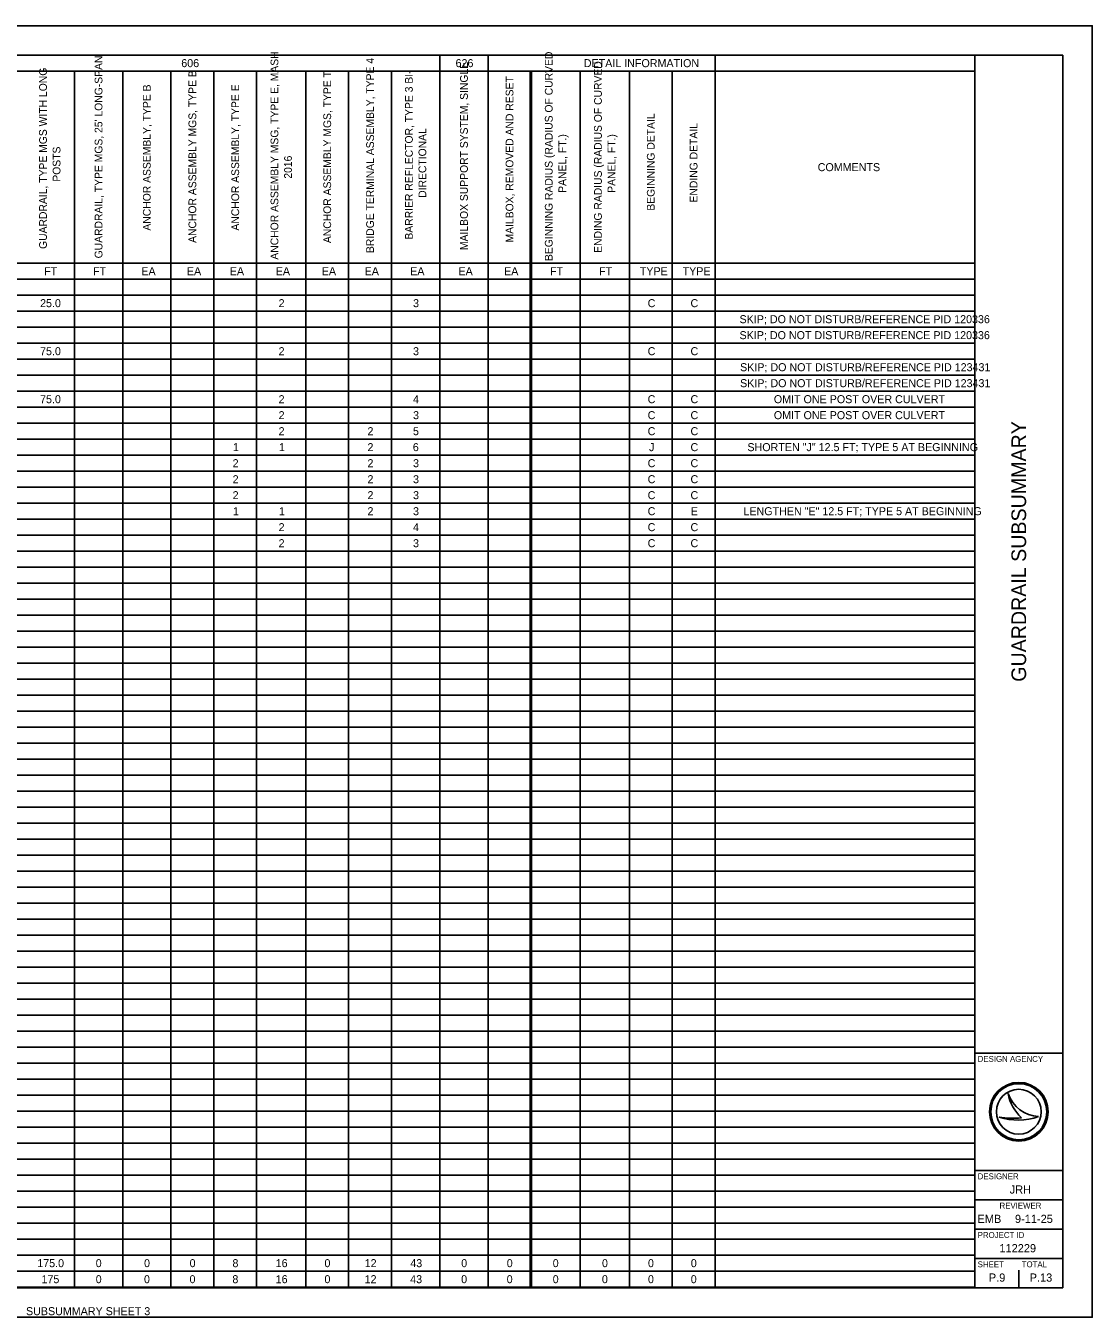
# Model space of a CAD drawing. Extents: x 0 to 34, y -0.3 to 22.
# Drawn here: x 15.84 to 34, y 0 to 22 of the extents above; entities that cross this region are included whole.
import ezdxf

# ---------------------------------------------------------------- set-up
doc = ezdxf.new("R2010")
doc.units = 0
for name, color, linetype in [('Default', 7, 'Continuous'), ('SH_Border', 7, 'Continuous'), ('SH_Cut_Line', 7, 'Continuous'), ('SH_Data', 7, 'Continuous')]:
    doc.layers.add(name, color=color, linetype=linetype)

msp = doc.modelspace()

# ---------------------------------------------------------------- linework, layer by layer
at = {"layer": 'Default'}
for p, q in [((1.5, 21.5), (31.999, 21.5)), ((22.888, 21.5), (22.888, 0.511)), ((23.711, 21.5), (23.711, 0.511)), ((27.576, 21.5), (27.576, 0.511)), ((31.999, 21.5), (31.999, 0.511)), ((5.582, 21.227), (24.451, 21.227)), ((16.664, 21.227), (16.664, 0.511)), ((17.487, 21.227), (17.487, 0.511)), ((18.31, 21.227), (18.31, 0.511)), ((19.039, 21.227), (19.039, 0.511)), ((19.769, 21.227), (19.769, 0.511)), ((20.607, 21.227), (20.607, 0.511)), ((21.336, 21.227), (21.336, 0.511)), ((22.066, 21.227), (22.066, 0.511)), ((24.43, 21.227), (31.999, 21.227)), ((24.43, 21.227), (24.43, 0.511)), ((24.451, 21.227), (24.451, 0.511)), ((25.279, 21.227), (25.279, 0.511)), ((26.117, 21.227), (26.117, 0.511)), ((26.846, 21.227), (26.846, 0.511)), ((5.582, 17.956), (24.43, 17.956)), ((24.451, 17.956), (31.999, 17.956)), ((1.5, 17.684), (24.43, 17.684)), ((24.451, 17.684), (31.999, 17.684)), ((1.5, 17.411), (24.43, 17.411)), ((24.451, 17.411), (31.999, 17.411)), ((1.5, 17.139), (24.43, 17.139)), ((24.451, 17.139), (31.999, 17.139)), ((1.5, 16.866), (24.43, 16.866)), ((24.451, 16.866), (31.999, 16.866)), ((1.5, 16.593), (24.43, 16.593)), ((24.451, 16.593), (31.999, 16.593)), ((1.5, 16.321), (24.43, 16.321)), ((24.451, 16.321), (31.999, 16.321)), ((1.5, 16.048), (24.43, 16.048)), ((24.451, 16.048), (31.999, 16.048)), ((1.5, 15.776), (24.43, 15.776)), ((24.451, 15.776), (31.999, 15.776)), ((1.5, 15.503), (24.43, 15.503)), ((24.451, 15.503), (31.999, 15.503)), ((1.5, 15.231), (24.43, 15.231)), ((24.451, 15.231), (31.999, 15.231)), ((1.5, 14.958), (24.43, 14.958)), ((24.451, 14.958), (31.999, 14.958)), ((1.5, 14.685), (24.43, 14.685)), ((24.451, 14.685), (31.999, 14.685)), ((1.5, 14.413), (24.43, 14.413)), ((24.451, 14.413), (31.999, 14.413)), ((1.5, 14.14), (24.43, 14.14)), ((24.451, 14.14), (31.999, 14.14)), ((1.5, 13.868), (24.43, 13.868)), ((24.451, 13.868), (31.999, 13.868)), ((1.5, 13.595), (24.43, 13.595)), ((24.451, 13.595), (31.999, 13.595)), ((1.5, 13.322), (24.43, 13.322)), ((24.451, 13.322), (31.999, 13.322)), ((1.5, 13.05), (24.43, 13.05)), ((24.451, 13.05), (31.999, 13.05)), ((1.5, 12.777), (24.43, 12.777)), ((24.451, 12.777), (31.999, 12.777)), ((1.5, 12.505), (24.43, 12.505)), ((24.451, 12.505), (31.999, 12.505)), ((1.5, 12.232), (24.43, 12.232)), ((24.451, 12.232), (31.999, 12.232)), ((1.5, 11.96), (24.43, 11.96)), ((24.451, 11.96), (31.999, 11.96)), ((1.5, 11.687), (24.43, 11.687)), ((24.451, 11.687), (31.999, 11.687)), ((1.5, 11.414), (24.43, 11.414)), ((24.451, 11.414), (31.999, 11.414)), ((1.5, 11.142), (24.43, 11.142)), ((24.451, 11.142), (31.999, 11.142)), ((1.5, 10.869), (24.43, 10.869)), ((24.451, 10.869), (31.999, 10.869)), ((1.5, 10.597), (24.43, 10.597)), ((24.451, 10.597), (31.999, 10.597)), ((1.5, 10.324), (24.43, 10.324)), ((24.451, 10.324), (31.999, 10.324)), ((1.5, 10.051), (24.43, 10.051)), ((24.451, 10.051), (31.999, 10.051)), ((1.5, 9.779), (24.43, 9.779)), ((24.451, 9.779), (31.999, 9.779)), ((1.5, 9.506), (24.43, 9.506)), ((24.451, 9.506), (31.999, 9.506)), ((1.5, 9.234), (24.43, 9.234)), ((24.451, 9.234), (31.999, 9.234)), ((1.5, 8.961), (24.43, 8.961)), ((24.451, 8.961), (31.999, 8.961)), ((1.5, 8.689), (24.43, 8.689)), ((24.451, 8.689), (31.999, 8.689)), ((1.5, 8.416), (24.43, 8.416)), ((24.451, 8.416), (31.999, 8.416)), ((1.5, 8.143), (24.43, 8.143)), ((24.451, 8.143), (31.999, 8.143)), ((1.5, 7.871), (24.43, 7.871)), ((24.451, 7.871), (31.999, 7.871)), ((1.5, 7.598), (24.43, 7.598)), ((24.451, 7.598), (31.999, 7.598)), ((1.5, 7.326), (24.43, 7.326)), ((24.451, 7.326), (31.999, 7.326)), ((1.5, 7.053), (24.43, 7.053)), ((24.451, 7.053), (31.999, 7.053)), ((1.5, 6.78), (24.43, 6.78)), ((24.451, 6.78), (31.999, 6.78)), ((1.5, 6.508), (24.43, 6.508)), ((24.451, 6.508), (31.999, 6.508)), ((1.5, 6.235), (24.43, 6.235)), ((24.451, 6.235), (31.999, 6.235)), ((1.5, 5.963), (24.43, 5.963)), ((24.451, 5.963), (31.999, 5.963)), ((1.5, 5.69), (24.43, 5.69)), ((24.451, 5.69), (31.999, 5.69)), ((1.5, 5.418), (24.43, 5.418)), ((24.451, 5.418), (31.999, 5.418)), ((1.5, 5.145), (24.43, 5.145)), ((24.451, 5.145), (31.999, 5.145)), ((1.5, 4.872), (24.43, 4.872)), ((24.451, 4.872), (31.999, 4.872)), ((1.5, 4.6), (24.43, 4.6)), ((24.451, 4.6), (31.999, 4.6)), ((1.5, 4.327), (24.43, 4.327)), ((24.451, 4.327), (31.999, 4.327)), ((1.5, 4.055), (24.43, 4.055)), ((24.451, 4.055), (31.999, 4.055)), ((1.5, 3.782), (24.43, 3.782)), ((24.451, 3.782), (31.999, 3.782)), ((1.5, 3.509), (24.43, 3.509)), ((24.451, 3.509), (31.999, 3.509)), ((1.5, 3.237), (24.43, 3.237)), ((24.451, 3.237), (31.999, 3.237)), ((1.5, 2.964), (24.43, 2.964)), ((24.451, 2.964), (31.999, 2.964)), ((1.5, 2.692), (24.43, 2.692)), ((24.451, 2.692), (31.999, 2.692)), ((1.5, 2.419), (24.43, 2.419)), ((24.451, 2.419), (31.999, 2.419)), ((1.5, 2.147), (24.43, 2.147)), ((24.451, 2.147), (31.999, 2.147)), ((1.5, 1.874), (24.43, 1.874)), ((24.451, 1.874), (31.999, 1.874)), ((1.5, 1.601), (24.43, 1.601)), ((24.451, 1.601), (31.999, 1.601)), ((1.5, 1.329), (24.43, 1.329)), ((24.451, 1.329), (31.999, 1.329)), ((1.5, 1.056), (24.43, 1.056)), ((24.451, 1.056), (31.999, 1.056)), ((5.582, 0.784), (24.43, 0.784)), ((24.451, 0.784), (27.576, 0.784)), ((27.576, 0.784), (31.999, 0.784)), ((1.5, 0.511), (24.451, 0.511)), ((24.43, 0.511), (27.576, 0.511)), ((27.576, 0.511), (31.999, 0.511))]:
    msp.add_line(p, q, dxfattribs=at)
at = {"layer": 'SH_Border'}
for p, q in [((32, 0.5), (32, 21.5)), ((32, 4.5), (33.5, 4.5)), ((32, 2.5), (33.5, 2.5)), ((32, 2), (33.5, 2)), ((32, 1.5), (33.5, 1.5)), ((32, 1), (33.5, 1))]:
    msp.add_line(p, q, dxfattribs=at)
msp.add_lwpolyline([(1.5, 21.5), (33.5, 21.5), (33.5, 0.5), (1.5, 0.5)], close=True, dxfattribs=at)
at = {"layer": 'SH_Cut_Line'}
msp.add_lwpolyline([(0, 0), (34, 0), (34, 22), (0, 22)], close=True, dxfattribs=at)
at = {"layer": 'SH_Data'}
for p, q in [((32.567, 3.81), (32.567, 3.81)), ((32.417, 3.41), (32.417, 3.41)), ((32.75, 3.5), (32.75, 3.5)), ((33.087, 3.419), (33.087, 3.419)), ((32.375, 0.675), (32.375, 0.675)), ((32.75, 0.5), (32.75, 0.8))]:
    msp.add_line(p, q, dxfattribs=at)
for radius in [0.5, 0.477, 0.477, 0.382]:
    msp.add_circle((32.75, 3.5), radius, dxfattribs=at)
for centre, radius, start, end in [((33.116, 3.998), 0.58, 198.9257, 198.9319), ((33.347, 3.97), 0.796, 191.6379, 191.6421), ((33.116, 3.998), 0.58, 198.9319, 267.1657), ((33.347, 3.97), 0.796, 191.6421, 226.0947), ((32.739, 4.37), 1.013, 251.4576, 290.0832), ((32.648, 4.654), 1.266, 259.4964, 259.4995), ((32.739, 4.37), 1.013, 251.4527, 251.4576), ((32.648, 4.654), 1.266, 259.4995, 276.6672)]:
    msp.add_arc(centre, radius, start, end, dxfattribs=at)

# ---------------------------------------------------------------- texts
at = {"layer": 'Default'}
for s, height, p in [("GUARDRAIL, TYPE MGS, 25' LONG-SPAN", 0.13193, (17.142, 18.038)), ('ANCHOR ASSEMBLY MSG, TYPE E, MASH ', 0.13193, (20.138, 18.016)), ('BRIDGE TERMINAL ASSEMBLY, TYPE 4', 0.13193, (21.767, 18.129)), ('MAILBOX SUPPORT SYSTEM, SINGLE', 0.13193, (23.366, 18.18)), ('BEGINNING RADIUS (RADIUS OF CURVED ', 0.13193, (24.81, 17.993)), ('ENDING RADIUS (RADIUS OF CURVED ', 0.13193, (25.648, 18.133)), ('GUARDRAIL, TYPE MGS WITH LONG ', 0.13193, (16.196, 18.199)), ('ANCHOR ASSEMBLY MGS, TYPE B', 0.13193, (18.74, 18.302)), ('ANCHOR ASSEMBLY MGS, TYPE T', 0.13193, (21.037, 18.298)), ('BARRIER REFLECTOR, TYPE 3 BI-', 0.13193, (22.428, 18.358)), ('MAILBOX, REMOVED AND RESET', 0.13193, (24.142, 18.309)), ('ANCHOR ASSEMBLY, TYPE B', 0.13193, (17.964, 18.511)), ('ANCHOR ASSEMBLY, TYPE E', 0.13193, (19.47, 18.512)), ('BEGINNING DETAIL', 0.13193, (26.548, 18.851)), ('DIRECTIONAL', 0.13193, (22.658, 19.07)), ('ENDING DETAIL', 0.13193, (27.277, 18.99)), ('PANEL, FT.)', 0.13193, (25.041, 19.155)), ('PANEL, FT.)', 0.13193, (25.879, 19.155)), ('POSTS', 0.1319, (16.427, 19.345)), ('2016', 0.1319, (20.369, 19.396))]:
    msp.add_text(s, height=height, rotation=90, dxfattribs=at).set_placement(p)
for s, height, p in [('606', 0.1363, (18.485, 21.296)), ('626', 0.1363, (23.157, 21.296)), ('DETAIL INFORMATION', 0.13629, (25.341, 21.296)), ('COMMENTS', 0.1363, (29.325, 19.524)), ('FT', 0.1363, (16.15, 17.752)), ('FT', 0.1363, (16.981, 17.752)), ('EA', 0.1363, (17.805, 17.752)), ('EA', 0.1363, (18.581, 17.752)), ('EA', 0.1363, (19.311, 17.752)), ('EA', 0.1363, (20.094, 17.752)), ('EA', 0.1363, (20.878, 17.752)), ('EA', 0.1363, (21.608, 17.752)), ('EA', 0.1363, (22.384, 17.752)), ('EA', 0.1363, (23.206, 17.752)), ('EA', 0.1363, (23.983, 17.752)), ('FT', 0.1363, (24.765, 17.752)), ('FT', 0.1363, (25.603, 17.752)), ('TYPE', 0.1363, (26.295, 17.752)), ('TYPE', 0.1363, (27.024, 17.752)), ('25.0', 0.1363, (16.08, 17.207)), ('2', 0.136, (20.143, 17.207)), ('3', 0.136, (22.433, 17.207)), ('C', 0.136, (26.429, 17.207)), ('C', 0.136, (27.159, 17.207)), ('SKIP; DO NOT DISTURB/REFERENCE PID 120336', 0.13629, (27.994, 16.934)), ('SKIP; DO NOT DISTURB/REFERENCE PID 120336', 0.13629, (27.994, 16.662)), ('75.0', 0.1363, (16.08, 16.389)), ('2', 0.136, (20.143, 16.389)), ('3', 0.136, (22.433, 16.389)), ('C', 0.136, (26.429, 16.389)), ('C', 0.136, (27.159, 16.389)), ('SKIP; DO NOT DISTURB/REFERENCE PID 123431', 0.13629, (28.003, 16.116)), ('SKIP; DO NOT DISTURB/REFERENCE PID 123431', 0.13629, (28.003, 15.844)), ('75.0', 0.1363, (16.08, 15.571)), ('2', 0.136, (20.143, 15.571)), ('4', 0.136, (22.433, 15.571)), ('C', 0.136, (26.429, 15.571)), ('C', 0.136, (27.159, 15.571)), ('OMIT ONE POST OVER CULVERT', 0.13629, (28.578, 15.571)), ('2', 0.136, (20.143, 15.299)), ('3', 0.136, (22.433, 15.299)), ('C', 0.136, (26.429, 15.299)), ('C', 0.136, (27.159, 15.299)), ('OMIT ONE POST OVER CULVERT', 0.13629, (28.578, 15.299)), ('2', 0.136, (20.143, 15.026)), ('2', 0.136, (21.657, 15.026)), ('5', 0.136, (22.432, 15.026)), ('C', 0.136, (26.429, 15.026)), ('C', 0.136, (27.159, 15.026)), ('1', 0.136, (19.365, 14.754)), ('1', 0.136, (20.149, 14.754)), ('2', 0.136, (21.657, 14.754)), ('6', 0.136, (22.429, 14.754)), ('J', 0.136, (26.452, 14.754)), ('C', 0.136, (27.159, 14.754)), ('SHORTEN "J" 12.5 FT; TYPE 5 AT BEGINNING', 0.13629, (28.128, 14.754)), ('2', 0.136, (19.36, 14.481)), ('2', 0.136, (21.657, 14.481)), ('3', 0.136, (22.433, 14.481)), ('C', 0.136, (26.429, 14.481)), ('C', 0.136, (27.159, 14.481)), ('2', 0.136, (19.36, 14.208)), ('2', 0.136, (21.657, 14.208)), ('3', 0.136, (22.433, 14.208)), ('C', 0.136, (26.429, 14.208)), ('C', 0.136, (27.159, 14.208)), ('2', 0.136, (19.36, 13.936)), ('2', 0.136, (21.657, 13.936)), ('3', 0.136, (22.433, 13.936)), ('C', 0.136, (26.429, 13.936)), ('C', 0.136, (27.159, 13.936)), ('1', 0.136, (19.365, 13.663)), ('1', 0.136, (20.149, 13.663)), ('2', 0.136, (21.657, 13.663)), ('3', 0.136, (22.433, 13.663)), ('C', 0.136, (26.429, 13.663)), ('E', 0.136, (27.164, 13.663)), ('LENGTHEN "E" 12.5 FT; TYPE 5 AT BEGINNING', 0.13629, (28.06, 13.663)), ('2', 0.136, (20.143, 13.391)), ('4', 0.136, (22.433, 13.391)), ('C', 0.136, (26.429, 13.391)), ('C', 0.136, (27.159, 13.391)), ('2', 0.136, (20.143, 13.118)), ('3', 0.136, (22.433, 13.118)), ('C', 0.136, (26.429, 13.118)), ('C', 0.136, (27.159, 13.118)), ('175.0', 0.1363, (16.032, 0.852)), ('0', 0.136, (17.028, 0.852)), ('0', 0.136, (17.851, 0.852)), ('0', 0.136, (18.627, 0.852)), ('8', 0.136, (19.357, 0.852)), ('16', 0.1363, (20.093, 0.852)), ('0', 0.136, (20.924, 0.852)), ('12', 0.1363, (21.609, 0.852)), ('43', 0.1363, (22.386, 0.852)), ('0', 0.136, (23.253, 0.852)), ('0', 0.136, (24.029, 0.852)), ('0', 0.136, (24.812, 0.852)), ('0', 0.136, (25.651, 0.852)), ('0', 0.136, (26.434, 0.852)), ('0', 0.136, (27.164, 0.852)), ('175', 0.1363, (16.104, 0.579)), ('0', 0.136, (17.028, 0.579)), ('0', 0.136, (17.85, 0.579)), ('0', 0.136, (18.626, 0.579)), ('8', 0.136, (19.356, 0.579)), ('16', 0.1363, (20.093, 0.579)), ('0', 0.136, (20.924, 0.579)), ('12', 0.1363, (21.608, 0.579)), ('43', 0.1363, (22.384, 0.579)), ('0', 0.136, (23.252, 0.579)), ('0', 0.136, (24.028, 0.579)), ('0', 0.136, (24.812, 0.579)), ('0', 0.136, (25.65, 0.579)), ('0', 0.136, (26.434, 0.579)), ('0', 0.136, (27.163, 0.579)), ('SUBSUMMARY SHEET 3', 0.13629, (15.84, 0.034))]:
    msp.add_text(s, height=height, dxfattribs=at).set_placement(p)
at = {"layer": 'SH_Data'}
msp.add_text('GUARDRAIL SUBSUMMARY', height=0.25, rotation=90, dxfattribs=at).set_placement((32.875, 10.825))
for s, height, p in [('DESIGN AGENCY', 0.1, (32.05, 4.35)), ('DESIGNER', 0.1, (32.05, 2.35)), ('JRH', 0.14, (32.595, 2.105)), ('REVIEWER', 0.1, (32.422, 1.85)), ('EMB', 0.14, (32.047, 1.605)), ('9-11-25', 0.14, (32.685, 1.605)), ('PROJECT ID', 0.1, (32.05, 1.35)), ('112229', 0.14, (32.42, 1.105)), ('SHEET', 0.1, (32.05, 0.85)), ('TOTAL', 0.1, (32.8, 0.85)), ('P.9', 0.14, (32.24, 0.605)), ('P.13', 0.14, (32.935, 0.605))]:
    msp.add_text(s, height=height, dxfattribs=at).set_placement(p)

doc.saveas('drawing.dxf')
